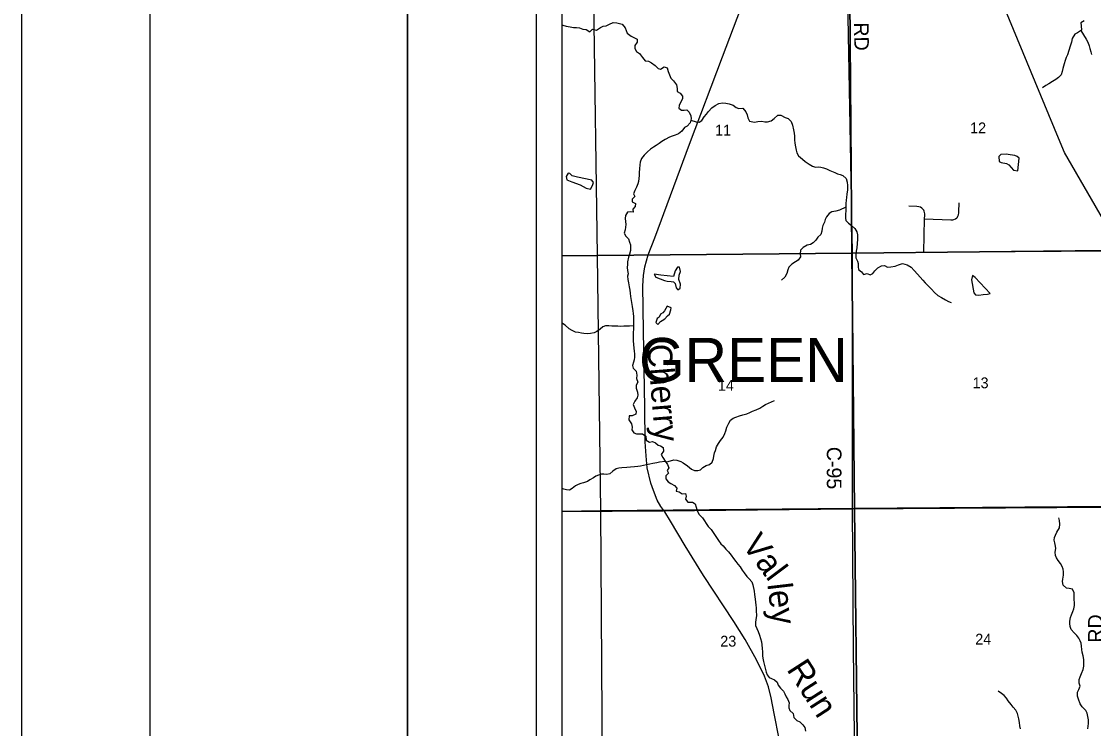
# Model space of a CAD drawing. Extents: x 0 to 36.9, y 0 to 22.
# Drawn here: x 0 to 4.166, y 16.582 to 19.328 of the extents above; entities that cross this region are included whole.
import ezdxf

# ---------------------------------------------------------------- set-up
doc = ezdxf.new("R2010")
doc.units = 0
for name, color, linetype in [('Default', 7, 'Continuous'), ('GM_X_County_Road', 7, 'Continuous'), ('GM_X_County_Road_Text', 7, 'Continuous'), ('GM_X_Minor_Lake', 7, 'Continuous'), ('GM_X_Minor_River', 7, 'Continuous'), ('GM_X_Minor_River_Text', 7, 'Continuous'), ('GM_X_Rail_Line', 7, 'Continuous'), ('GM_X_Section', 7, 'Continuous'), ('GM_X_Section_Text', 7, 'Continuous'), ('GM_X_State_Route', 7, 'Continuous'), ('GM_X_Township_Road', 7, 'Continuous'), ('GM_X_Township_Text', 7, 'Continuous'), ('SH_Border', 7, 'Continuous'), ('SH_Cut_Line', 7, 'Continuous'), ('SH_Data', 7, 'Continuous')]:
    doc.layers.add(name, color=color, linetype=linetype)

msp = doc.modelspace()

# ---------------------------------------------------------------- linework, layer by layer
at = {"layer": 'Default'}
for points in [[(2.1, 19.4072), (2.1, 18.4183), (2.2385, 18.4199), (2.2245, 19.4084)], [(2.1, 18.4183), (2.1, 17.4248), (2.2509, 17.4272), (2.2385, 18.4199)], [(2.1, 17.4248), (2.1, 16.4306), (2.2574, 16.4325), (2.2509, 17.4272)]]:
    msp.add_lwpolyline(points, close=True, dxfattribs=at)
at = {"layer": 'GM_X_County_Road'}
msp.add_lwpolyline([(3.21, 19.4177), (3.2275, 18.4294), (3.2285, 17.4352), (3.232, 16.893), (3.2368, 16.4429)], dxfattribs=at)
at = {"layer": 'GM_X_Minor_Lake'}
for points in [[(3.8767, 18.7967), (3.8689, 18.8038), (3.8598, 18.8071), (3.8415, 18.8102), (3.8259, 18.813), (3.8054, 18.8115), (3.7976, 18.8034), (3.7994, 18.7841), (3.8071, 18.7808), (3.8276, 18.777), (3.8365, 18.771), (3.8554, 18.7501), (3.8721, 18.748)], [(3.8721, 18.748), (3.8767, 18.7967)], [(2.1403, 18.7286), (2.1314, 18.7383), (2.1238, 18.7393), (2.1168, 18.7259), (2.1193, 18.7134), (2.1384, 18.7054), (2.1705, 18.6934), (2.1938, 18.6805), (2.2106, 18.6773), (2.2195, 18.6915), (2.2227, 18.7026), (2.2161, 18.7123)], [(2.2161, 18.7123), (2.1612, 18.7239), (2.1403, 18.7286)], [(2.4841, 18.3433), (2.459, 18.3463), (2.4645, 18.335), (2.4813, 18.3285), (2.4981, 18.3219), (2.5092, 18.319), (2.524, 18.3181), (2.5339, 18.3175), (2.5401, 18.3108), (2.5446, 18.2934), (2.55, 18.2859), (2.5594, 18.2918), (2.561, 18.3074), (2.555, 18.3263), (2.5563, 18.343), (2.561, 18.3567), (2.5576, 18.3738), (2.5497, 18.3736), (2.5404, 18.3594), (2.5339, 18.3381)], [(2.5339, 18.3381), (2.4841, 18.3433)], [(3.7063, 18.3344), (3.6959, 18.341), (3.692, 18.3246), (3.7004, 18.2739), (3.7074, 18.2664), (3.7207, 18.2655), (3.7374, 18.2676), (3.7537, 18.2687), (3.7646, 18.2719)], [(3.7646, 18.2719), (3.7063, 18.3344)], [(2.5089, 18.2225), (2.4986, 18.2045), (2.4919, 18.1961), (2.4828, 18.1914), (2.4785, 18.1799), (2.4702, 18.1741), (2.4648, 18.1591), (2.4729, 18.1517), (2.4837, 18.1629), (2.4897, 18.1672), (2.4999, 18.1734), (2.511, 18.185), (2.5178, 18.1919), (2.5228, 18.2076), (2.5246, 18.216)], [(2.5246, 18.216), (2.5089, 18.2225)]]:
    msp.add_lwpolyline(points, dxfattribs=at)
at = {"layer": 'GM_X_Minor_River'}
for points in [[(4.129, 19.3306), (4.117, 19.3231), (4.118, 19.311), (4.1186, 19.2951), (4.104, 19.2842), (4.0931, 19.2783), (4.0828, 19.2618), (4.0796, 19.2481), (4.0745, 19.2328), (4.0692, 19.216), (4.0641, 19.1992), (4.0598, 19.1885), (4.0554, 19.177), (4.0511, 19.1633), (4.0469, 19.1454), (4.044, 19.1336), (4.0397, 19.1213), (4.0293, 19.1101), (4.0188, 19.1031), (4.0064, 19.0957), (3.9921, 19.0863), (3.9801, 19.0793), (3.967, 19.0703)], [(2.1, 19.3143), (2.104, 19.3137), (2.117, 19.3101), (2.1326, 19.307), (2.1452, 19.3053), (2.1569, 19.3047), (2.168, 19.3034), (2.1817, 19.2979), (2.1947, 19.297), (2.2081, 19.2884), (2.2193, 19.2989), (2.2342, 19.295), (2.2496, 19.3043), (2.2609, 19.3094), (2.2726, 19.3115), (2.2854, 19.3178), (2.2997, 19.3237), (2.3134, 19.3225), (2.3241, 19.3207), (2.334, 19.3179), (2.3453, 19.3036), (2.35, 19.2927), (2.354, 19.2825), (2.369, 19.2706), (2.3827, 19.2651), (2.3927, 19.2592), (2.3925, 19.2474), (2.3836, 19.2347), (2.3834, 19.2237), (2.3904, 19.2113), (2.4016, 19.2035), (2.4128, 19.1885), (2.4241, 19.175), (2.4366, 19.174), (2.4485, 19.167), (2.4623, 19.1566), (2.4735, 19.1454), (2.4831, 19.1429), (2.4969, 19.1526), (2.5095, 19.1483), (2.5136, 19.1343), (2.518, 19.1214), (2.5235, 19.1086), (2.5343, 19.0974), (2.5459, 19.082), (2.5481, 19.068), (2.5483, 19.0558), (2.5601, 19.0492), (2.5691, 19.0383), (2.5692, 19.0284), (2.5641, 19.0181), (2.556, 19.0016), (2.5539, 18.9921), (2.565, 18.9836), (2.5753, 18.9833), (2.5851, 18.9846), (2.5951, 18.9765), (2.6011, 18.9617), (2.6024, 18.95), (2.5981, 18.9347), (2.5862, 18.9216), (2.576, 18.9161), (2.5656, 18.9023), (2.5529, 18.8914), (2.5401, 18.8867), (2.5287, 18.8831), (2.5178, 18.8783), (2.5008, 18.8701), (2.4885, 18.8615), (2.478, 18.8538), (2.4663, 18.8471), (2.4558, 18.8405), (2.4445, 18.8323), (2.4326, 18.8215), (2.4191, 18.8087), (2.4091, 18.7956), (2.4044, 18.7823), (2.4026, 18.772), (2.401, 18.7556), (2.4005, 18.7419), (2.3999, 18.7305), (2.399, 18.718), (2.3972, 18.707), (2.3951, 18.697), (2.3904, 18.6848), (2.3834, 18.6718), (2.3787, 18.6588), (2.3834, 18.6482), (2.3726, 18.6386), (2.3731, 18.6279), (2.3858, 18.6209), (2.3841, 18.6095), (2.3755, 18.5995)], [(4.1159, 19.2931), (4.1375, 19.259), (4.143, 19.2473), (4.1486, 19.2334), (4.1518, 19.2228), (4.1551, 19.2107), (4.1575, 19.1997)], [(2.6008, 18.9443), (2.6216, 18.9381), (2.6334, 18.9376), (2.6435, 18.9442), (2.6524, 18.958), (2.6617, 18.968), (2.6703, 18.9788), (2.6826, 18.9923), (2.6957, 19.0024), (2.7092, 19.0102), (2.7247, 19.0128), (2.7369, 19.0107), (2.7503, 19.0082), (2.7651, 19.0035), (2.7774, 18.9939), (2.7881, 18.9906), (2.8025, 18.9916), (2.8142, 18.9774), (2.82, 18.9657), (2.8225, 18.9543), (2.8288, 18.9411), (2.8482, 18.9365), (2.8619, 18.9394), (2.8766, 18.9404), (2.8884, 18.9387), (2.8991, 18.9389), (2.9127, 18.9429), (2.9254, 18.9511), (2.9389, 18.9638), (2.951, 18.964), (2.9671, 18.9552), (2.979, 18.9508), (2.9909, 18.9396), (2.9965, 18.9249), (3.0006, 18.9078), (3.0027, 18.895), (3.0033, 18.8824), (3.0039, 18.8688), (3.0048, 18.8555), (3.0077, 18.8411), (3.0098, 18.829), (3.0134, 18.8177), (3.0197, 18.8067), (3.0343, 18.7933), (3.0451, 18.7847), (3.0612, 18.7744), (3.0743, 18.7658), (3.0853, 18.7626), (3.0956, 18.7632), (3.1066, 18.7622), (3.1169, 18.7593), (3.1276, 18.7553), (3.1406, 18.7491), (3.1601, 18.741), (3.1712, 18.737), (3.1815, 18.7338), (3.1918, 18.7298), (3.2041, 18.7182), (3.2085, 18.7038), (3.2095, 18.6906), (3.2098, 18.6742), (3.2078, 18.6579), (3.2053, 18.6445), (3.204, 18.6346), (3.2027, 18.6209), (3.2033, 18.6058), (3.2032, 18.5928), (3.2022, 18.5795), (3.2017, 18.5643), (3.203, 18.5548), (3.2131, 18.5448), (3.2254, 18.5355), (3.2377, 18.5239), (3.2455, 18.5115), (3.248, 18.499), (3.2483, 18.4827), (3.2478, 18.4659), (3.2462, 18.4496), (3.2437, 18.4355), (3.2417, 18.4218), (3.2419, 18.4096), (3.2485, 18.3976), (3.251, 18.3877), (3.2508, 18.3752), (3.2521, 18.365), (3.264, 18.3553), (3.2714, 18.3455), (3.2862, 18.3488), (3.298, 18.3448), (3.3078, 18.3495), (3.3156, 18.3592), (3.3279, 18.3719), (3.3418, 18.379), (3.3536, 18.3803), (3.3651, 18.374), (3.3784, 18.3754), (3.3946, 18.3779), (3.4078, 18.3831), (3.4241, 18.3887), (3.4412, 18.3836), (3.4573, 18.374)], [(2.3755, 18.5995), (2.3772, 18.5881), (2.3658, 18.5891), (2.3552, 18.587), (2.347, 18.5751), (2.3457, 18.5629), (2.3478, 18.5519), (2.348, 18.5394), (2.347, 18.5299), (2.3457, 18.5188), (2.3414, 18.5062), (2.3484, 18.4942), (2.3584, 18.4837), (2.3632, 18.4716), (2.366, 18.4607), (2.3666, 18.4485), (2.3664, 18.4386), (2.3628, 18.4242), (2.3588, 18.4123), (2.3546, 18.3944), (2.3544, 18.3849), (2.3542, 18.3731), (2.3548, 18.361), (2.3569, 18.3481), (2.3555, 18.3386), (2.3561, 18.326), (2.3586, 18.3132), (2.3619, 18.2976), (2.3636, 18.2848), (2.3653, 18.2726), (2.3663, 18.2597), (2.3692, 18.2446), (2.3734, 18.2211), (2.3756, 18.2044), (2.3769, 18.1946), (2.3778, 18.1828), (2.3784, 18.1703), (2.3786, 18.1593), (2.3785, 18.1448), (2.3779, 18.1315), (2.3773, 18.1216), (2.3767, 18.1121), (2.3771, 18.0874), (2.3781, 18.0734), (2.3795, 18.0597), (2.3812, 18.0472), (2.3821, 18.0374), (2.382, 18.0248), (2.3806, 18.0146), (2.3781, 18.005), (2.3746, 17.9917), (2.377, 17.9818), (2.389, 17.9706), (2.3915, 17.9551), (2.3902, 17.9418), (2.3957, 17.9274), (2.3891, 17.9152), (2.3886, 17.9034), (2.3941, 17.889), (2.3954, 17.8773), (2.3926, 17.8666), (2.3829, 17.8535), (2.3775, 17.8401), (2.3826, 17.8281), (2.3881, 17.8137), (2.3868, 17.8031), (2.3736, 17.796), (2.3615, 17.7969), (2.3602, 17.781), (2.37, 17.7659), (2.3725, 17.7527), (2.3722, 17.7424), (2.3789, 17.7304), (2.39, 17.726), (2.4025, 17.7262), (2.4135, 17.726), (2.4266, 17.7171), (2.4276, 17.7015), (2.4399, 17.6937), (2.4523, 17.697), (2.4631, 17.6911), (2.4742, 17.6822), (2.4838, 17.68), (2.4933, 17.6741), (2.4944, 17.6589), (2.4862, 17.6466), (2.4921, 17.6342), (2.5015, 17.6199), (2.51, 17.6075), (2.5159, 17.5947), (2.5096, 17.5843), (2.514, 17.5741), (2.5036, 17.563), (2.5037, 17.5523), (2.5127, 17.5396), (2.5238, 17.5333), (2.5376, 17.5259), (2.5461, 17.5158), (2.5436, 17.5036), (2.5562, 17.5011), (2.567, 17.4941)], [(3.2033, 18.6067), (3.1788, 18.5951), (3.1641, 18.5918), (3.149, 18.5885), (3.1384, 18.5823), (3.1276, 18.57), (3.1236, 18.5596), (3.1207, 18.5493), (3.1141, 18.5359), (3.1116, 18.526), (3.11, 18.5135), (3.1056, 18.5005), (3.0944, 18.4904), (3.0862, 18.4785), (3.0762, 18.4681), (3.0656, 18.4626), (3.0535, 18.4594), (3.0373, 18.4507), (3.0273, 18.4396), (3.0256, 18.4262), (3.0266, 18.4137), (3.018, 18.4014), (3.0071, 18.3952), (2.9929, 18.3851), (2.9817, 18.3739), (2.9781, 18.3632), (2.9745, 18.3487), (2.966, 18.3352), (2.9537, 18.3229)], [(3.4573, 18.374), (3.4686, 18.3605), (3.4813, 18.347), (3.4921, 18.3354), (3.5022, 18.3238), (3.5119, 18.3134), (3.5215, 18.3029), (3.5366, 18.2879), (3.5482, 18.2756), (3.5613, 18.2644), (3.5755, 18.2555), (3.59, 18.2474), (3.6019, 18.2407), (3.6122, 18.2364)], [(2.3785, 18.1462), (2.3625, 18.1453), (2.3504, 18.1451), (2.3401, 18.1442), (2.3291, 18.144), (2.317, 18.1446), (2.3056, 18.1448), (2.2946, 18.1453), (2.2824, 18.1459), (2.2699, 18.1457), (2.2586, 18.1417), (2.2484, 18.1336), (2.2361, 18.1243), (2.2251, 18.1191), (2.2108, 18.1162), (2.199, 18.1153), (2.1857, 18.1162), (2.1762, 18.1172), (2.164, 18.1197), (2.153, 18.1221), (2.14, 18.1276), (2.1285, 18.1339), (2.1131, 18.1485), (2.1023, 18.1551), (2.1, 18.1557)], [(2.5039, 17.6164), (2.5344, 17.625), (2.5469, 17.6241), (2.5622, 17.6194), (2.5718, 17.6138), (2.5879, 17.602), (2.6033, 17.5893), (2.6156, 17.5842), (2.6281, 17.5844), (2.6383, 17.5868), (2.648, 17.5953), (2.6608, 17.6031), (2.6732, 17.6079), (2.6834, 17.6161), (2.6892, 17.6306), (2.6909, 17.6405), (2.6934, 17.6527), (2.6963, 17.6622), (2.701, 17.6764), (2.708, 17.689), (2.7165, 17.7013), (2.7269, 17.7136), (2.7331, 17.7274), (2.7364, 17.7389), (2.7411, 17.7522), (2.7488, 17.7683), (2.7554, 17.7791), (2.7652, 17.7876), (2.7753, 17.7919), (2.7905, 17.796), (2.8037, 17.8), (2.8184, 17.8048), (2.8305, 17.8099), (2.8406, 17.8143), (2.8546, 17.8194), (2.8685, 17.8261), (2.8813, 17.8343), (2.8915, 17.8402), (2.9031, 17.8457), (2.9144, 17.8512), (2.9261, 17.8556)], [(2.5019, 17.6192), (2.4791, 17.6165), (2.4685, 17.6144), (2.453, 17.6115), (2.4417, 17.6094), (2.4288, 17.6066), (2.4175, 17.6037), (2.4057, 17.6013), (2.3948, 17.5992), (2.3815, 17.5982), (2.3663, 17.5968), (2.3519, 17.5962), (2.3329, 17.5951), (2.3208, 17.5934), (2.3103, 17.5902), (2.2982, 17.582), (2.2859, 17.5708), (2.2749, 17.5687), (2.2635, 17.57), (2.2533, 17.5699), (2.2423, 17.5663), (2.2322, 17.5616), (2.2224, 17.5561), (2.2088, 17.5479), (2.1991, 17.542), (2.1844, 17.5365), (2.1738, 17.5332), (2.1628, 17.5296), (2.153, 17.5245), (2.1399, 17.5137), (2.1302, 17.5082), (2.118, 17.5088), (2.1077, 17.5116), (2.1, 17.5137)], [(2.567, 17.4941), (2.5799, 17.4947), (2.5827, 17.4849), (2.5806, 17.4734), (2.5888, 17.4606), (2.5986, 17.4608), (2.6081, 17.4613), (2.6177, 17.4543), (2.6217, 17.4418), (2.6258, 17.4278), (2.6332, 17.4131), (2.646, 17.4004), (2.6541, 17.3884), (2.6604, 17.3786), (2.6686, 17.3662), (2.6794, 17.3546), (2.6872, 17.3429), (2.6981, 17.3272), (2.7085, 17.3129), (2.7175, 17.2998), (2.7271, 17.2915), (2.7376, 17.2792), (2.7469, 17.2687), (2.7573, 17.2559), (2.7674, 17.2424), (2.7756, 17.2308), (2.7841, 17.2199), (2.7923, 17.2094), (2.8008, 17.197), (2.8079, 17.1861), (2.8191, 17.173), (2.8276, 17.1633), (2.8377, 17.1516), (2.8424, 17.1399), (2.8466, 17.1157), (2.8487, 17.102), (2.8509, 17.0846), (2.8519, 17.0725), (2.854, 17.0615), (2.8549, 17.0512), (2.8555, 17.041), (2.8558, 17.0193), (2.8542, 17.006), (2.8525, 16.9942), (2.8526, 16.9828), (2.857, 16.9703), (2.8622, 16.959), (2.8677, 16.9443), (2.8714, 16.9311), (2.875, 16.9182), (2.8771, 16.9068), (2.8784, 16.8932), (2.8791, 16.8795), (2.8801, 16.8647), (2.8814, 16.8552), (2.8839, 16.8424), (2.8863, 16.8321), (2.89, 16.8163), (2.8933, 16.8004), (2.8973, 16.7902), (2.905, 16.78), (2.9146, 16.776), (2.9257, 16.7716), (2.9368, 16.7627), (2.9404, 16.751), (2.9498, 16.7382), (2.9606, 16.727), (2.9668, 16.7172), (2.9712, 16.7051), (2.9782, 16.695), (2.983, 16.6814), (2.9824, 16.6719), (2.9818, 16.662), (2.9861, 16.6522), (2.9981, 16.6398), (3.001, 16.6247), (3.0133, 16.6135), (3.0248, 16.6076), (3.0356, 16.5968), (3.0442, 16.5855), (3.0463, 16.5722)], [(4.1431, 16.5802), (4.1448, 16.5913), (4.1458, 16.6019), (4.1459, 16.6164), (4.1441, 16.6289), (4.1416, 16.6414), (4.1358, 16.6519), (4.1222, 16.6664), (4.1144, 16.6785), (4.1069, 16.6958), (4.1036, 16.7075), (4.1033, 16.7234), (4.1092, 16.7338), (4.1135, 16.7468), (4.1103, 16.7577), (4.11, 16.7718), (4.1144, 16.7825), (4.1195, 16.7955), (4.126, 16.8112), (4.1277, 16.8237), (4.1283, 16.8348), (4.1284, 16.8507), (4.1258, 16.8643), (4.1218, 16.8787), (4.1204, 16.8889), (4.1195, 16.9018), (4.1177, 16.9132), (4.1134, 16.923), (4.109, 16.9335), (4.1009, 16.9436), (4.0904, 16.9533), (4.0788, 16.9672), (4.0752, 16.9777), (4.0734, 16.9895), (4.0736, 16.999), (4.0764, 17.0127), (4.0797, 17.0234), (4.0851, 17.036), (4.0895, 17.0475), (4.0915, 17.0604), (4.0921, 17.0711), (4.0911, 17.0813), (4.0902, 17.0915), (4.0906, 17.1086), (4.0836, 17.1229), (4.0706, 17.1257), (4.0603, 17.1278), (4.0483, 17.1386), (4.0447, 17.1526), (4.0464, 17.1625), (4.0491, 17.1777), (4.0493, 17.1903), (4.0476, 17.2005), (4.044, 17.2118), (4.0369, 17.2235), (4.0284, 17.2347), (4.0225, 17.2449), (4.0178, 17.2546), (4.0172, 17.2668), (4.0188, 17.2809), (4.0182, 17.2907), (4.0154, 17.3032), (4.0133, 17.3142), (4.0138, 17.3241), (4.0175, 17.3336), (4.0233, 17.3444), (4.0329, 17.362), (4.0346, 17.3753), (4.0331, 17.3901), (4.0314, 17.4003)], [(3.8817, 16.5805), (3.88, 16.5919), (3.8775, 16.6051), (3.875, 16.6192), (3.8733, 16.6302), (3.8704, 16.6407), (3.8642, 16.6528), (3.8541, 16.6656), (3.8452, 16.6757), (3.8339, 16.6895), (3.827, 16.6993), (3.818, 16.7106), (3.8077, 16.718), (3.7957, 16.7265)]]:
    msp.add_lwpolyline(points, dxfattribs=at)
at = {"layer": 'GM_X_Rail_Line'}
for points in [[(4.2428, 16.065), (4.2237, 16.806), (4.2214, 17.442), (4.2174, 18.4382), (4.22, 18.531), (4.2124, 19.4314), (4.2095, 19.5156), (4.1742, 20.5119), (3.4355, 20.4995), (3.1942, 20.4953), (2.6054, 20.4898), (2.1, 20.4802), (2.1, 14.4405)], [(2.9441, 16.542), (2.925, 16.6399), (2.9129, 16.7017), (2.903, 16.7436), (2.8871, 16.7856), (2.8567, 16.8483), (2.8116, 16.9276), (2.7682, 16.9981), (2.6505, 17.176), (2.5786, 17.2919), (2.522, 17.3871), (2.4995, 17.424), (2.4843, 17.444), (2.4705, 17.4691), (2.4561, 17.5059), (2.446, 17.5346), (2.4317, 17.5942), (2.4269, 17.6406), (2.4237, 17.6957), (2.4218, 17.8287), (2.4174, 18.1262), (2.415, 18.3011), (2.4175, 18.3422), (2.4222, 18.3752), (2.435, 18.4214), (2.4605, 18.4873), (2.5963, 18.8521), (2.7245, 19.1906), (2.8955, 19.6426)]]:
    msp.add_lwpolyline(points, dxfattribs=at)
at = {"layer": 'GM_X_Section'}
for points in [[(2.2245, 19.4084), (3.2188, 19.419), (3.226, 18.4277), (2.2385, 18.4199)], [(4.212, 19.4289), (4.2176, 18.508), (4.219, 18.4391), (3.226, 18.4277), (3.2188, 19.419)], [(2.2385, 18.4199), (3.226, 18.4277), (3.2373, 17.4365), (2.2509, 17.4272)], [(4.219, 18.4391), (4.2298, 17.4831), (4.2298, 17.4444), (3.2373, 17.4365), (3.226, 18.4277)], [(2.2509, 17.4272), (3.2373, 17.4365), (3.2483, 16.4396), (2.2574, 16.4325)], [(4.2298, 17.4444), (4.2381, 16.4858), (4.2388, 16.4513), (3.2483, 16.4396), (3.2373, 17.4365)]]:
    msp.add_lwpolyline(points, close=True, dxfattribs=at)
at = {"layer": 'GM_X_State_Route'}
msp.add_line((2.1, 17.4243), (2.4919, 17.4281), dxfattribs=at)
for points in [[(4.2202, 18.5304), (4.0532, 18.8191), (4.0295, 18.8744), (3.802, 19.4268)], [(2.4919, 17.4281), (3.2285, 17.4352), (4.2216, 17.4415)]]:
    msp.add_lwpolyline(points, dxfattribs=at)
at = {"layer": 'GM_X_Township_Road'}
for points in [[(3.5094, 18.5617), (3.6107, 18.5582), (3.6144, 18.5579), (3.6191, 18.5583), (3.6235, 18.5594), (3.6288, 18.5618), (3.634, 18.5657), (3.6366, 18.5684), (3.639, 18.5719), (3.6415, 18.5774), (3.6427, 18.5848), (3.6428, 18.5893), (3.6434, 18.6232)], [(3.5067, 18.4318), (3.5094, 18.5617), (3.5097, 18.5765), (3.51, 18.5813), (3.5096, 18.5859), (3.5082, 18.5909), (3.5061, 18.5952), (3.5031, 18.5994), (3.4985, 18.6036), (3.4934, 18.6066), (3.4864, 18.6088), (3.4794, 18.6091), (3.4482, 18.6103)], [(2.1, 18.4182), (3.2275, 18.4294), (3.5067, 18.4318), (4.2176, 18.4377)]]:
    msp.add_lwpolyline(points, dxfattribs=at)
at = {"layer": 'SH_Border'}
for points in [[(0.5, 21.5), (1.5, 21.5), (1.5, 0.5), (0.5, 0.5)], [(1.5, 21.5), (33.5, 21.5), (33.5, 0.5), (1.5, 0.5)]]:
    msp.add_lwpolyline(points, close=True, dxfattribs=at)
at = {"layer": 'SH_Cut_Line'}
msp.add_lwpolyline([(0, 0), (34, 0), (34, 22), (0, 22)], close=True, dxfattribs=at)
msp.add_lwpolyline([(8.9, 14.5158), (8.9, 20.9), (2.1, 20.9), (2.1, 14.4405)], dxfattribs=at)
at = {"layer": 'SH_Data'}
for p, q in [((2, 21), (2, 14)), ((2.1, 20.9), (2.1, 14.1))]:
    msp.add_line(p, q, dxfattribs=at)

# ---------------------------------------------------------------- texts
at = {"layer": 'GM_X_County_Road_Text'}
for s, rotation, p in [('RD', 270.9872, (3.2347, 19.324)), ('C-95', 270, (3.1295, 17.6761)), ('RD', 90.4937, (4.2017, 16.9159))]:
    msp.add_text(s, height=0.05682, rotation=rotation, dxfattribs=at).set_placement(p)
at = {"layer": 'GM_X_Minor_River_Text'}
for s, height, rotation, p in [('Cherry', 0.09475, 274.7538, (2.431, 18.072)), ('Val', 0.09476, 306.7488, (2.7972, 17.2947)), ('ley', 0.09476, 276.7611, (2.8981, 17.1429)), ('Run', 0.09476, 302.752, (2.971, 16.8118))]:
    msp.add_text(s, height=height, rotation=rotation, dxfattribs=at).set_placement(p)
at = {"layer": 'GM_X_Section_Text'}
for s, p in [('11', (2.6953, 18.8853)), ('12', (3.6861, 18.894)), ('14', (2.7061, 17.894)), ('13', (3.6957, 17.9037)), ('23', (2.7153, 16.9003)), ('24', (3.7061, 16.9081))]:
    msp.add_text(s, height=0.04186, rotation=0, dxfattribs=at).set_placement(p)
at = {"layer": 'GM_X_Township_Text'}
msp.add_text('GREEN', height=0.17045, rotation=0, dxfattribs=at).set_placement((2.3998, 17.9285))

doc.saveas('drawing.dxf')
